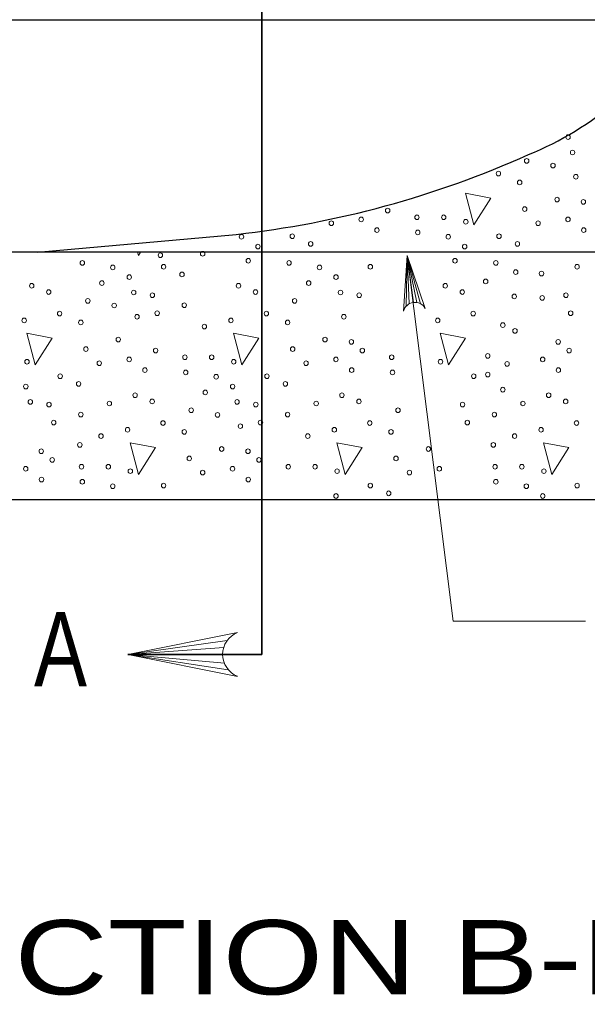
# Model space of a CAD drawing. Extents: x -410.5 to -376.5, y 1617.6 to 1661.6.
# Drawn here: x -393.247 to -391.413, y 1650.531 to 1653.682 of the extents above; entities that cross this region are included whole.
import ezdxf

# ---------------------------------------------------------------- set-up
doc = ezdxf.new("R2010")
doc.units = 0
doc.header["$LTSCALE"] = 0.062
doc.layers.add('1', color=7, linetype='Continuous', lineweight=13)

msp = doc.modelspace()

# ---------------------------------------------------------------- linework, layer by layer
at = {"layer": '1', "lineweight": 35}
for p, q in [((-392.4645, 1651.77717), (-392.4645, 1655.833)), ((-392.4645, 1651.63225), (-392.4645, 1651.77717)), ((-392.4645, 1651.63225), (-392.89717, 1651.63225))]:
    msp.add_line(p, q, dxfattribs=at)
at = {"layer": '1', "lineweight": 25}
for p, q in [((-393.83325, 1653.681), (-391.09567, 1653.681)), ((-393.18867, 1652.9315), (-392.54683, 1652.9885))]:
    msp.add_line(p, q, dxfattribs=at)
at = {"layer": '1'}
for p, q in [((-391.99875, 1652.7565), (-391.99483, 1652.92042)), ((-391.97525, 1652.76858), (-391.99483, 1652.92042)), ((-391.98917, 1652.76392), (-391.99483, 1652.92042)), ((-391.96383, 1652.76833), (-391.99483, 1652.92042)), ((-391.95217, 1652.76442), (-391.99483, 1652.92042)), ((-392.57667, 1651.67708), (-392.89717, 1651.63225)), ((-392.5875, 1651.65492), (-392.89717, 1651.63225)), ((-392.59083, 1651.63225), (-392.89717, 1651.63225)), ((-392.58517, 1651.60342), (-392.89717, 1651.63225)), ((-392.57283, 1651.58267), (-392.89717, 1651.63225))]:
    msp.add_line(p, q, dxfattribs=at)
at = {"layer": '1', "lineweight": 25}
for points in [[(-391.09567, 1653.681), (-391.09567, 1652.9315), (-393.18867, 1652.9315)], [(-390.15167, 1652.9315), (-394.16367, 1652.9315), (-394.16367, 1652.78158), (-393.83325, 1652.78158), (-393.83325, 1652.63167), (-394.27908, 1652.63167), (-394.54583, 1652.78158), (-394.77725, 1652.78158)], [(-394.77725, 1652.78158), (-394.77725, 1652.13192), (-390.15167, 1652.13192)]]:
    msp.add_lwpolyline(points, dxfattribs=at)
at = {"layer": '1'}
for points in [[(-391.807, 1653.12133), (-391.78, 1653.01892), (-391.725, 1653.10533)], [(-393.22367, 1652.66925), (-393.19667, 1652.56683), (-393.14167, 1652.65333)], [(-392.55608, 1652.66925), (-392.52917, 1652.56683), (-392.47425, 1652.65333)], [(-391.88858, 1652.66925), (-391.86167, 1652.56683), (-391.80667, 1652.65333)], [(-392.88992, 1652.31592), (-392.86292, 1652.21358), (-392.80792, 1652.3)], [(-392.22242, 1652.31592), (-392.19542, 1652.21358), (-392.14042, 1652.3)], [(-391.55483, 1652.31592), (-391.52783, 1652.21358), (-391.47292, 1652.3)]]:
    msp.add_lwpolyline(points, close=True, dxfattribs=at)
for points in [[(-392.86583, 1652.93158), (-392.86292, 1652.92025), (-392.85567, 1652.93158)], [(-392.00733, 1652.74042), (-391.99483, 1652.92042), (-391.93717, 1652.74942)], [(-391.99483, 1652.92042), (-391.84717, 1651.7395), (-391.41975, 1651.7395)], [(-392.54317, 1651.56142), (-392.89717, 1651.63225), (-392.54317, 1651.703)]]:
    msp.add_lwpolyline(points, dxfattribs=at)
for centre, radius, start, end in [((-391.97037, 1652.73073), 0.0382, 29.42671, 165.25284), ((-392.51454, 1651.6323), 0.0764, 112.08782, 247.91395)]:
    msp.add_arc(centre, radius, start, end, dxfattribs=at)
at = {"layer": '1', "lineweight": 25}
for centre, major_axis, start_param, end_param in [((-391.98484, 1654.29513), (0, 1.12397), 3.5092821, 4.1343748), ((-392.89445, 1656.47964), (0, -3.51046), 0.105032, 0.4000009)]:
    msp.add_ellipse(centre, major_axis=major_axis, ratio=0.944543, start_param=start_param, end_param=end_param, dxfattribs=at)
at = {"layer": '1'}
for centre, major_axis in [((-391.47588, 1653.30254), (0, 0.00756)), ((-391.46142, 1653.25296), (0, 0.00756)), ((-391.60955, 1653.22593), (0, 0.00756)), ((-391.52456, 1653.21097), (0, 0.00756)), ((-391.70061, 1653.18488), (0, 0.00756)), ((-391.63208, 1653.15626), (0, 0.00756)), ((-391.45069, 1653.17469), (0, 0.00756)), ((-391.51132, 1653.10096), (0, 0.00756)), ((-391.42627, 1653.0936), (0, 0.00756)), ((-392.05834, 1653.06562), (0, -0.00756)), ((-391.61584, 1653.07039), (0, 0.00756)), ((-392.24007, 1653.02457), (0, 0.00756)), ((-392.14367, 1653.037), (0, 0.00756)), ((-391.96372, 1653.04366), (0, -0.00756)), ((-391.87717, 1653.04366), (0, 0.00756)), ((-391.80602, 1653.02934), (0, -0.00756)), ((-391.57256, 1653.02457), (0, 0.00756)), ((-391.47616, 1653.037), (0, 0.00756)), ((-392.09288, 1653.00231), (0, -0.00756)), ((-391.96105, 1652.99501), (0, -0.00756)), ((-391.42538, 1653.00231), (0, -0.00756)), ((-392.53027, 1652.9807), (0, 0.00756)), ((-392.36628, 1652.98258), (0, -0.00756)), ((-392.30682, 1652.95779), (0, -0.00756)), ((-391.86276, 1652.9807), (0, 0.00756)), ((-391.69878, 1652.98258), (0, -0.00756)), ((-391.63931, 1652.95779), (0, -0.00756)), ((-392.65548, 1652.92586), (0, 0.00756)), ((-392.47715, 1652.94919), (0, 0.00756)), ((-391.80964, 1652.94919), (0, 0.00756)), ((-393.04397, 1652.8963), (0, -0.00756)), ((-392.79193, 1652.92122), (0, -0.00756)), ((-392.5083, 1652.9036), (0, -0.00756)), ((-392.37647, 1652.8963), (0, -0.00756)), ((-391.84079, 1652.9036), (0, -0.00756)), ((-391.70896, 1652.8963), (0, -0.00756)), ((-392.94568, 1652.88199), (0, 0.00756)), ((-392.7817, 1652.88387), (0, -0.00756)), ((-392.27818, 1652.88199), (0, 0.00756)), ((-392.11419, 1652.88387), (0, -0.00756)), ((-391.64491, 1652.86675), (0, -0.00756)), ((-391.5617, 1652.86212), (0, -0.00756)), ((-391.44668, 1652.88387), (0, -0.00756)), ((-392.98089, 1652.8314), (0, 0.00756)), ((-392.89256, 1652.85048), (0, 0.00756)), ((-392.72224, 1652.85908), (0, -0.00756)), ((-392.31339, 1652.8314), (0, 0.00756)), ((-392.22505, 1652.85048), (0, 0.00756)), ((-391.74198, 1652.83666), (0, -0.00756)), ((-393.20735, 1652.82251), (0, -0.00756)), ((-393.15239, 1652.80248), (0, -0.00756)), ((-392.8781, 1652.80089), (0, 0.00756)), ((-392.53984, 1652.82251), (0, -0.00756)), ((-392.48488, 1652.80248), (0, -0.00756)), ((-392.21059, 1652.80089), (0, 0.00756)), ((-391.87233, 1652.82251), (0, -0.00756)), ((-391.81737, 1652.80248), (0, -0.00756)), ((-393.02623, 1652.77386), (0, 0.00756)), ((-392.81774, 1652.79224), (0, -0.00756)), ((-392.35872, 1652.77386), (0, 0.00756)), ((-392.15024, 1652.79224), (0, -0.00756)), ((-391.64953, 1652.78804), (0, -0.00756)), ((-391.55939, 1652.78342), (0, -0.00756)), ((-391.48273, 1652.79224), (0, -0.00756)), ((-392.94123, 1652.7589), (0, 0.00756)), ((-392.715, 1652.75979), (0, -0.00756)), ((-393.23171, 1652.71085), (0, -0.00756)), ((-393.11729, 1652.73281), (0, 0.00756)), ((-393.04876, 1652.70419), (0, 0.00756)), ((-392.86736, 1652.72263), (0, 0.00756)), ((-392.80245, 1652.73411), (0, -0.00756)), ((-392.5642, 1652.71085), (0, -0.00756)), ((-392.44978, 1652.73281), (0, 0.00756)), ((-392.38125, 1652.70419), (0, 0.00756)), ((-392.19985, 1652.72263), (0, 0.00756)), ((-391.89669, 1652.71085), (0, -0.00756)), ((-391.78227, 1652.73281), (0, 0.00756)), ((-391.46743, 1652.73411), (0, -0.00756)), ((-392.64987, 1652.69082), (0, -0.00756)), ((-391.68652, 1652.69545), (0, -0.00756)), ((-391.64722, 1652.67694), (0, -0.00756)), ((-392.92799, 1652.64889), (0, 0.00756)), ((-392.26049, 1652.64889), (0, 0.00756)), ((-392.17543, 1652.64153), (0, 0.00756)), ((-391.50793, 1652.64153), (0, 0.00756)), ((-393.03252, 1652.61833), (0, 0.00756)), ((-392.80751, 1652.61356), (0, -0.00756)), ((-392.36501, 1652.61833), (0, 0.00756)), ((-392.14, 1652.61356), (0, -0.00756)), ((-391.47249, 1652.61356), (0, -0.00756)), ((-393.2227, 1652.57728), (0, -0.00756)), ((-392.89284, 1652.58494), (0, 0.00756)), ((-392.71289, 1652.59159), (0, -0.00756)), ((-392.62634, 1652.59159), (0, 0.00756)), ((-392.55519, 1652.57728), (0, -0.00756)), ((-392.22533, 1652.58494), (0, 0.00756)), ((-392.04538, 1652.59159), (0, -0.00756)), ((-391.88768, 1652.57728), (0, -0.00756)), ((-391.73505, 1652.59592), (0, -0.00756)), ((-391.55782, 1652.58494), (0, 0.00756)), ((-392.98924, 1652.57251), (0, 0.00756)), ((-392.84205, 1652.55025), (0, -0.00756)), ((-392.32173, 1652.57251), (0, 0.00756)), ((-392.17454, 1652.55025), (0, -0.00756)), ((-391.67265, 1652.57046), (0, -0.00756)), ((-391.50704, 1652.55025), (0, -0.00756)), ((-393.11545, 1652.53052), (0, -0.00756)), ((-392.71022, 1652.54295), (0, -0.00756)), ((-392.61193, 1652.52864), (0, 0.00756)), ((-392.44794, 1652.53052), (0, -0.00756)), ((-392.04271, 1652.54295), (0, -0.00756)), ((-391.78044, 1652.53052), (0, -0.00756)), ((-391.73505, 1652.53573), (0, -0.00756)), ((-393.22632, 1652.49713), (0, 0.00756)), ((-393.05599, 1652.50573), (0, -0.00756)), ((-392.55881, 1652.49713), (0, 0.00756)), ((-392.38848, 1652.50573), (0, -0.00756)), ((-391.68652, 1652.48712), (0, -0.00756)), ((-392.87359, 1652.46916), (0, -0.00756)), ((-392.64714, 1652.47805), (0, 0.00756)), ((-392.20608, 1652.46916), (0, -0.00756)), ((-391.53858, 1652.46916), (0, -0.00756)), ((-393.21185, 1652.44754), (0, 0.00756)), ((-393.1515, 1652.43889), (0, -0.00756)), ((-392.95653, 1652.44248), (0, -0.00756)), ((-392.81863, 1652.44913), (0, -0.00756)), ((-392.69248, 1652.42051), (0, 0.00756)), ((-392.54434, 1652.44754), (0, 0.00756)), ((-392.48399, 1652.43889), (0, -0.00756)), ((-392.28902, 1652.44248), (0, -0.00756)), ((-392.15113, 1652.44913), (0, -0.00756)), ((-392.02497, 1652.42051), (0, 0.00756)), ((-391.81648, 1652.43889), (0, -0.00756)), ((-391.62151, 1652.44248), (0, -0.00756)), ((-391.48362, 1652.44913), (0, -0.00756)), ((-393.04876, 1652.40644), (0, -0.00756)), ((-392.60748, 1652.40555), (0, 0.00756)), ((-392.38125, 1652.40644), (0, -0.00756)), ((-391.71374, 1652.40644), (0, -0.00756)), ((-393.1362, 1652.38076), (0, -0.00756)), ((-392.89796, 1652.3575), (0, -0.00756)), ((-392.78353, 1652.37946), (0, 0.00756)), ((-392.53361, 1652.36928), (0, 0.00756)), ((-392.46869, 1652.38076), (0, -0.00756)), ((-392.23045, 1652.3575), (0, -0.00756)), ((-392.11603, 1652.37946), (0, 0.00756)), ((-391.80118, 1652.38076), (0, -0.00756)), ((-391.56294, 1652.3575), (0, -0.00756)), ((-391.44852, 1652.37946), (0, 0.00756)), ((-392.98362, 1652.33747), (0, -0.00756)), ((-392.715, 1652.35084), (0, 0.00756)), ((-392.31611, 1652.33747), (0, -0.00756)), ((-392.0475, 1652.35084), (0, 0.00756)), ((-391.6486, 1652.33747), (0, -0.00756)), ((-393.05204, 1652.30885), (0, -0.00756)), ((-392.59424, 1652.29554), (0, 0.00756)), ((-391.92673, 1652.29554), (0, 0.00756)), ((-391.71702, 1652.30885), (0, -0.00756)), ((-393.1767, 1652.28818), (0, 0.00756)), ((-392.69876, 1652.26498), (0, 0.00756)), ((-392.50919, 1652.28818), (0, 0.00756)), ((-392.03125, 1652.26498), (0, 0.00756)), ((-393.22659, 1652.23159), (0, 0.00756)), ((-393.14126, 1652.26021), (0, -0.00756)), ((-393.04664, 1652.23824), (0, -0.00756)), ((-392.96009, 1652.23824), (0, 0.00756)), ((-392.55908, 1652.23159), (0, 0.00756)), ((-392.47376, 1652.26021), (0, -0.00756)), ((-392.37914, 1652.23824), (0, -0.00756)), ((-392.29258, 1652.23824), (0, 0.00756)), ((-391.89158, 1652.23159), (0, 0.00756)), ((-391.71163, 1652.23824), (0, -0.00756)), ((-391.62507, 1652.23824), (0, 0.00756)), ((-392.88895, 1652.22393), (0, -0.00756)), ((-392.65548, 1652.21916), (0, 0.00756)), ((-392.22144, 1652.22393), (0, -0.00756)), ((-391.98798, 1652.21916), (0, 0.00756)), ((-391.55393, 1652.22393), (0, -0.00756)), ((-393.17581, 1652.1969), (0, -0.00756)), ((-393.04397, 1652.1896), (0, -0.00756)), ((-392.94568, 1652.17529), (0, 0.00756)), ((-392.7817, 1652.17717), (0, -0.00756)), ((-392.5083, 1652.1969), (0, -0.00756)), ((-392.11419, 1652.17717), (0, -0.00756)), ((-391.70896, 1652.1896), (0, -0.00756)), ((-391.61067, 1652.17529), (0, 0.00756)), ((-391.44668, 1652.17717), (0, -0.00756)), ((-392.22505, 1652.14378), (0, 0.00756)), ((-392.05473, 1652.15238), (0, -0.00756)), ((-391.55754, 1652.14378), (0, 0.00756))]:
    msp.add_ellipse(centre, major_axis=major_axis, ratio=0.944543, dxfattribs=at)

# ---------------------------------------------------------------- texts
for s, width, p in [('A', 0.8, (-393.20008, 1651.52867)), ('SECTION B-B', 1.3, (-393.81975, 1650.53425))]:
    msp.add_text(s, height=0.24, dxfattribs=dict(at, width=width)).set_placement(p)

doc.saveas('drawing.dxf')
